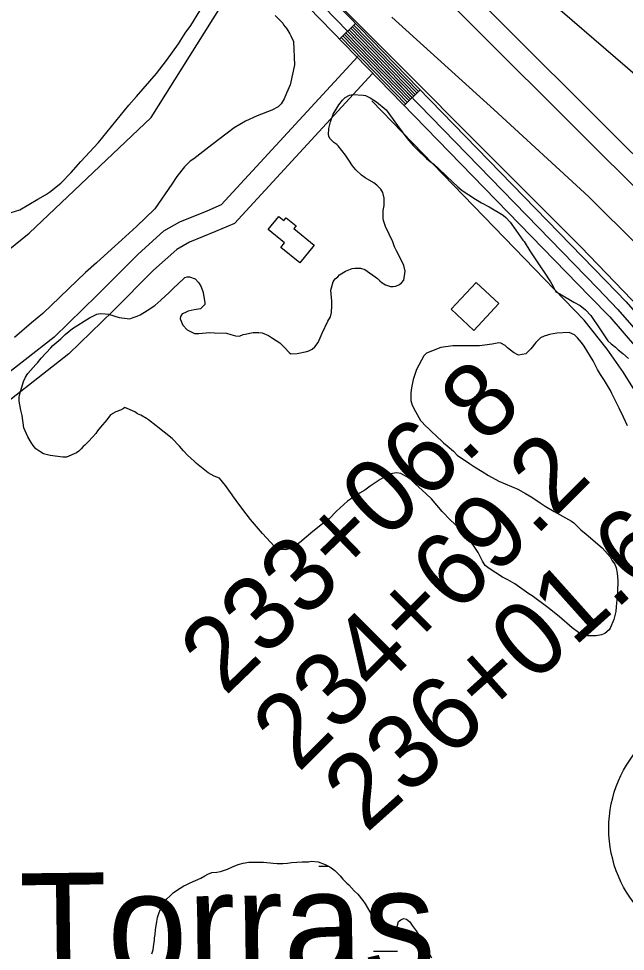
# Model space of a CAD drawing. Extents: x 3146026 to 3183936, y 897894 to 923344.
# Drawn here: x 3171939 to 3172756, y 904310 to 905566 of the extents above; entities that cross this region are included whole.
import ezdxf

# ---------------------------------------------------------------- set-up
doc = ezdxf.new("R2010")
doc.units = 0
for name, color, linetype in [('V-BLDG-OTLN', 7, 'Continuous'), ('V-LEVE-TOET', 7, 'Continuous'), ('V-ROAD-CNTR', 7, 'Continuous'), ('V-ROAD-IDEN', 7, 'Continuous'), ('V-SITE-VEGE', 7, 'Continuous'), ('V-SURV-IDEN', 7, 'Continuous'), ('V-SURV-LINE', 7, 'Continuous'), ('V-TOPO-GNAM-IDEN', 7, 'Continuous'), ('V-TOPO-SHOR', 7, 'Continuous'), ('V-WETL-SWMP', 7, 'Continuous')]:
    doc.layers.add(name, color=color, linetype=linetype)

msp = doc.modelspace()

# ---------------------------------------------------------------- linework, layer by layer
at = {"layer": 'V-BLDG-OTLN'}
for points in [[(3172275, 905281.9), (3172289.4, 905299.6), (3172296, 905294.2), (3172299.1, 905298), (3172312.7, 905287.1), (3172309.6, 905283.3), (3172337, 905261.1), (3172317.5, 905237.1), (3172292, 905257.7), (3172297.1, 905264)], [(3172552, 905146.3), (3172521.5, 905174.7), (3172555.3, 905210.8), (3172585.7, 905182.4)]]:
    msp.add_lwpolyline(points, close=True, dxfattribs=at)
at = {"layer": 'V-LEVE-TOET'}
for points in [[(3172529.3, 905786.4), (3172531.3, 905781.5), (3172531.4, 905768.5), (3172528.9, 905753.2), (3172526.2, 905732.1), (3172532.9, 905716.1), (3172545.6, 905698.2), (3172564.6, 905678.8), (3172610, 905628.6), (3172788.2, 905474.5), (3172938.4, 905328), (3173044.4, 905215.5), (3173079.4, 905167.6), (3173157, 905054.6), (3173211.7, 904943.1), (3173306.6, 904778.2), (3173401.4, 904667.1), (3173480.5, 904547.5), (3173582.5, 904366.5)], [(3173393.9, 904268.1), (3173391.5, 904277.3), (3173381.5, 904302.7), (3173333.9, 904388.2), (3173230.5, 904565), (3173129.1, 904747.2), (3173057.9, 904869.1), (3172963.8, 905015.7), (3172850.9, 905169.6), (3172773.3, 905260.1), (3172706.8, 905326.1), (3172578.8, 905443.6), (3172441.8, 905567.9)]]:
    msp.add_lwpolyline(points, dxfattribs=at)
at = {"layer": 'V-ROAD-CNTR'}
for p, q in [((3172392.7, 905559.4), (3172371.2, 905538.5)), ((3172479.9, 905469.9), (3172458.4, 905448.9))]:
    msp.add_line(p, q, dxfattribs=at)
for points in [[(3171485.1, 906491), (3171511.5, 906466.1), (3171767.2, 906202.4), (3172729.8, 905213), (3172757.1, 905184.7), (3172794.3, 905142), (3172820.4, 905108.8), (3172848.9, 905069.2)], [(3171474.8, 906480.1), (3171501, 906455.4), (3171756.4, 906191.9), (3172719.1, 905202.5), (3172746, 905174.6), (3172782.8, 905132.4), (3172808.4, 905099.8), (3172836.8, 905060.4)], [(3171464.5, 906469.2), (3171490.4, 906444.7), (3171745.7, 906181.5), (3172708.3, 905192.1), (3172735, 905164.5), (3172771.2, 905122.8), (3172796.5, 905090.8), (3172824.6, 905051.6)], [(3172386.3, 905553.2), (3172473.4, 905463.6)], [(3172388.4, 905555.3), (3172475.6, 905465.7)], [(3172390.6, 905557.4), (3172477.7, 905467.8)], [(3172373.4, 905540.6), (3172460.5, 905451)], [(3172375.5, 905542.7), (3172462.7, 905453.1)], [(3172377.7, 905544.8), (3172464.8, 905455.2)], [(3172379.8, 905546.9), (3172467, 905457.3)], [(3172382, 905549), (3172469.1, 905459.4)], [(3172384.1, 905551.1), (3172471.3, 905461.5)], [(3172396, 905515), (3172211.9, 905315.3), (3172192.5, 905307), (3172155.8, 905292), (3172134.3, 905279.8), (3172100.1, 905248.9), (3172044.7, 905193.6), (3171987, 905137.1), (3171869.2, 905045.4), (3171843.9, 905026.8), (3171662.8, 904836), (3171344.9, 904497.8), (3171046.7, 904177.6), (3170924, 904055.8), (3170905, 904037), (3170884.8, 904020.2), (3170828.3, 903983.6), (3170772.5, 903951.5), (3170747.9, 903934.6), (3170726, 903916.2), (3170692.1, 903883.8), (3170452.4, 903624.8)], [(3172415.7, 905492.1), (3172229.6, 905290.3), (3172204.1, 905279.4), (3172169, 905264.9), (3172152, 905255.3), (3172120.8, 905227.2), (3172065.8, 905172.2), (3172006.8, 905114.5), (3171887.3, 905021.5), (3171863.9, 905004.2), (3171684.6, 904815.4), (3171366.8, 904477.3), (3171068.2, 904156.7), (3170945.1, 904034.5), (3170925.2, 904014.7), (3170902.5, 903996), (3170844, 903958), (3170788.5, 903926.1), (3170766, 903910.7), (3170746, 903893.9), (3170713.5, 903862.8), (3170474.1, 903604)]]:
    msp.add_lwpolyline(points, dxfattribs=at)
at = {"layer": 'V-ROAD-IDEN'}
msp.add_circle((3172898.8, 904475.6), 165, dxfattribs=at)
at = {"layer": 'V-SITE-VEGE'}
for points in [[(3172284.4, 905570.1), (3172294.9, 905560), (3172295.8, 905557.6), (3172300.1, 905552.3), (3172304.4, 905545.5), (3172305.8, 905542.7), (3172309.1, 905535), (3172310.4, 905503.8), (3172308.9, 905495.2), (3172304.5, 905477), (3172299.6, 905465.5), (3172296.7, 905457.8), (3172292.8, 905451.1), (3172288.5, 905447.3), (3172279.8, 905442.6), (3172260.1, 905435), (3172244.7, 905427.9), (3172229.3, 905418.9), (3172219.7, 905411.7), (3172199, 905396), (3172174.9, 905377.4), (3172170.1, 905374.1), (3172162.4, 905366.5), (3172152.2, 905353.6), (3172145.5, 905343.1), (3172122.3, 905310.1), (3172097.7, 905286.2), (3172077.9, 905268.1), (3172063.9, 905255.7), (3172043.7, 905237.1), (3172029.2, 905224.3), (3171971.8, 905169), (3171956.4, 905156.6), (3171933.7, 905136.5)], [(3172022.8, 905373.5), (3172046.5, 905399.2), (3172087.5, 905449.4), (3172097.7, 905461.3), (3172124.7, 905492.3), (3172138.2, 905509.5), (3172154.2, 905532), (3172163.4, 905546.3), (3172171.1, 905556.8), (3172183.2, 905576.4)], [(3172202.9, 905143.2), (3172218.9, 905142.4), (3172224.6, 905140.6), (3172231, 905138.8), (3172236, 905138.4), (3172239.6, 905139.8), (3172241.4, 905140.9), (3172243.9, 905141.2), (3172255, 905143.3), (3172262.5, 905143.6), (3172267.1, 905142.9), (3172275.3, 905139.3), (3172281, 905136), (3172290.9, 905129.5), (3172294.8, 905125.6), (3172296.9, 905123.1), (3172303.3, 905116.3), (3172305.8, 905114.5), (3172314, 905115.1), (3172327.2, 905117.9), (3172329.7, 905118.6), (3172334.4, 905121.1), (3172337.9, 905124.3), (3172342.2, 905130), (3172347.7, 905142.4), (3172355.6, 905158.8), (3172358.8, 905164.5), (3172360.3, 905170.2), (3172360.7, 905179.8), (3172360.7, 905185.8), (3172359.4, 905200.5), (3172362.7, 905211.5), (3172364.1, 905214), (3172365.5, 905215.8), (3172368.8, 905218.6), (3172371.3, 905221.1), (3172379.2, 905226), (3172388.1, 905229.5), (3172392, 905230.2), (3172399.5, 905230.2), (3172405.2, 905228.4), (3172422.2, 905216.2), (3172425.4, 905212.9), (3172428.6, 905210.4), (3172432.9, 905207.5), (3172440, 905205.4), (3172443.2, 905205.3), (3172446.8, 905206), (3172451.8, 905208.2), (3172454.7, 905210.3), (3172457.9, 905213.8), (3172459.7, 905225.9), (3172457.6, 905233.8), (3172453.8, 905242), (3172447.8, 905253.5), (3172445.3, 905258.8), (3172442.8, 905265.3), (3172433, 905286.3), (3172430.5, 905294.2), (3172429.8, 905297.4), (3172429.9, 905307.8), (3172431.3, 905314.2), (3172431.4, 905324.5), (3172429.7, 905332), (3172426.8, 905336.3), (3172421.2, 905342), (3172417.3, 905344.9), (3172405.9, 905351.7), (3172400.9, 905355.3), (3172393.1, 905362.5), (3172388.5, 905367.9), (3172383.6, 905375.4), (3172379.3, 905382.2), (3172369.4, 905394.7), (3172367.6, 905396.5), (3172363.7, 905399.4), (3172361.2, 905401.6), (3172358, 905404.8), (3172356.6, 905407.6), (3172356.3, 905410.1), (3172356.7, 905418), (3172358.9, 905427.2), (3172362.5, 905437.2), (3172369, 905447.9), (3172370.1, 905450), (3172375.1, 905456), (3172378.7, 905459.6), (3172384.8, 905462.8), (3172389, 905463.8), (3172402.9, 905463), (3172406.1, 905462.3), (3172412.5, 905459.4), (3172421.1, 905454), (3172433.8, 905443.2), (3172449.4, 905422.1), (3172461.8, 905404.9), (3172470.3, 905395.2), (3172476, 905389.2), (3172488.4, 905377.7), (3172493.4, 905373.7), (3172498, 905370.1)], [(3171917.4, 905301.2), (3171940.5, 905308.7), (3171965, 905323), (3171975.1, 905328.7), (3171980.4, 905332.5), (3171995.8, 905344.4), (3172009.8, 905358.7), (3172022.8, 905373.5)], [(3172498, 905370.1), (3172504, 905364.8), (3172515.7, 905353.6), (3172530.3, 905339.6), (3172536.3, 905334.6), (3172554.4, 905322.8), (3172562.2, 905318.1), (3172572.9, 905312.7), (3172591.7, 905301.2), (3172595.3, 905298.3), (3172600.9, 905291.8), (3172608.4, 905281.4), (3172617.9, 905267.8), (3172619.7, 905266.1), (3172627.5, 905253.2), (3172641.6, 905231.7), (3172646.9, 905224.5), (3172655.4, 905211.7), (3172658.9, 905205.2)], [(3172219.9, 904934.2), (3172217.8, 904937.4), (3172213.6, 904942.4), (3172209.7, 904947.4), (3172202.5, 904950), (3172194.4, 904954.6), (3172178.4, 904967.2), (3172175.6, 904970.1), (3172166.3, 904978.3), (3172161, 904984.1), (3172155.7, 904990.5), (3172145.8, 905000.9), (3172124.1, 905017.8), (3172113.8, 905026), (3172111.3, 905027.8), (3172103.5, 905032.2), (3172099.2, 905034), (3172095.7, 905036.5), (3172082.2, 905042.6), (3172080.4, 905041.2), (3172076.1, 905039.1), (3172070, 905036.6), (3172062.9, 905032.4), (3172057.8, 905026), (3172049.2, 905016.1), (3172045.3, 905011.1), (3172042.8, 905007.5), (3172038.8, 905002.9), (3172032.7, 904996.2), (3172028.1, 904991.9), (3172025.9, 904989.8), (3172023.4, 904987), (3172020.2, 904983.8), (3172016.9, 904981.3), (3172003.7, 904975.7), (3171998.4, 904975.7), (3171981.6, 904977.9), (3171972.4, 904980.1), (3171967.4, 904983.4), (3171962.4, 904987), (3171958.5, 904991.3), (3171956.1, 904995.2), (3171951.5, 905003.1), (3171946.2, 905015.2), (3171943.8, 905031.6), (3171942, 905039.1), (3171939.6, 905050.9), (3171939.6, 905056.3), (3171940.7, 905060.9), (3171945.5, 905077.3), (3171948.3, 905083.3), (3171951.6, 905088.3), (3171962, 905100.3), (3171964.5, 905102.8), (3171969.2, 905108.9), (3171982.4, 905122.7), (3171985.3, 905125.9), (3171995.7, 905134.7), (3172001.8, 905140.8), (3172011.8, 905148.9), (3172034.4, 905163.1), (3172044.4, 905168), (3172049, 905169), (3172055.4, 905168.6), (3172060.1, 905167.9), (3172074.3, 905163.5), (3172088.9, 905162), (3172093.2, 905163.8), (3172098.6, 905165.6), (3172102.5, 905167.3), (3172112.1, 905173), (3172122.5, 905180), (3172126.5, 905183.2), (3172130.4, 905186.8), (3172136.9, 905192.8), (3172141.2, 905196.7), (3172146.9, 905202), (3172154.8, 905209.8), (3172161.2, 905215.5), (3172163, 905217.3), (3172165.9, 905218.3), (3172169.1, 905218.3), (3172176.9, 905215.7), (3172181.9, 905210.4), (3172184.7, 905205), (3172187.5, 905197.1), (3172189.6, 905183.2), (3172189.6, 905181.1), (3172183.8, 905175.4), (3172175.3, 905174), (3172167.4, 905172.3), (3172162.8, 905169.8), (3172159.2, 905168.4), (3172157, 905165.2), (3172156.7, 905161.7), (3172160.2, 905153.1), (3172166.2, 905147), (3172175.8, 905142.3), (3172181.5, 905142.3), (3172196.5, 905143.3), (3172202.9, 905143.2)], [(3172658.9, 905205.2), (3172662.5, 905198.1), (3172667.8, 905195.5), (3172686.6, 905184.4), (3172695.2, 905179.7), (3172702.6, 905174), (3172709.7, 905166.1), (3172721.7, 905148.5), (3172732.7, 905132.4), (3172737, 905128.1), (3172742.6, 905123.5), (3172746.2, 905120.2), (3172752.6, 905115.2), (3172760.4, 905108.4)], [(3172758.8, 905017.8), (3172753.5, 905029.3), (3172747.9, 905041.4), (3172738, 905061.1), (3172735.9, 905065.4), (3172728.1, 905079), (3172722.5, 905086.8), (3172718.6, 905093.6), (3172712.6, 905105.1), (3172700.6, 905125.1), (3172697, 905129.8), (3172691.7, 905136.2), (3172687.8, 905140.2), (3172680.3, 905143.4), (3172663.9, 905142.4), (3172653.9, 905140.7), (3172651.1, 905140), (3172646.8, 905138.6), (3172641.8, 905136.1), (3172635.7, 905129.8), (3172628.9, 905121.6), (3172622.1, 905114.9), (3172612.1, 905113.1), (3172605.3, 905116.4), (3172597.5, 905122.8), (3172594.3, 905126.1), (3172588.3, 905129.3), (3172585.8, 905129.7), (3172576.9, 905127.9), (3172559.7, 905125.5), (3172540.1, 905125.7), (3172531.6, 905125.3), (3172523.7, 905125.4), (3172507.7, 905123.3)], [(3172507.7, 905123.3), (3172488.4, 905115.6), (3172484.8, 905112.1), (3172474.7, 905093.6), (3172470.3, 905080), (3172468.1, 905069), (3172467, 905062.2), (3172467.3, 905051.9), (3172469.1, 905045.5), (3172473.3, 905037.2), (3172480.4, 905025.1), (3172481.8, 905023.3), (3172486.7, 905018.3), (3172492.1, 905013.2), (3172496.3, 905008.9), (3172500.6, 905005.4), (3172511.2, 904995), (3172516.2, 904991), (3172524.7, 904983.5), (3172529.7, 904978.4), (3172546, 904966.9), (3172552.8, 904962.6), (3172563.4, 904956.2), (3172571.9, 904950.8), (3172585.8, 904943.5), (3172611.4, 904932.4), (3172621.7, 904926.9), (3172630.3, 904921.9), (3172641.3, 904914), (3172648, 904909.7), (3172660.1, 904902.5), (3172683.6, 904889.5), (3172686.8, 904887), (3172696.3, 904877.7), (3172703.1, 904871.9), (3172724.7, 904853.6), (3172735.4, 904841.5), (3172738.5, 904836.1), (3172741.7, 904831.4), (3172743.8, 904826.8), (3172745.2, 904819.3), (3172745.9, 904809.7), (3172745.4, 904794), (3172744.7, 904786.5), (3172744.7, 904783.6), (3172743.5, 904774.4), (3172743.2, 904768), (3172740.6, 904756.9), (3172735.5, 904745.2), (3172734.1, 904743), (3172728.4, 904738.4), (3172724.1, 904736.3), (3172716.9, 904734.9), (3172705.5, 904735), (3172695.6, 904738.3), (3172693.1, 904739.7), (3172684.6, 904745.8), (3172666.8, 904760.9), (3172651.9, 904773.1), (3172630.6, 904788.9), (3172626.3, 904791.4), (3172607.1, 904805.1), (3172597.6, 904810.5), (3172590.8, 904814.1), (3172572.7, 904825.6), (3172567.4, 904829.9), (3172563.8, 904835.6), (3172557.8, 904847.1), (3172543, 904869.3), (3172525.2, 904886.8), (3172520.6, 904890.8), (3172509.6, 904902.3), (3172502.2, 904910.9), (3172494.8, 904919.5), (3172488, 904926.3), (3172472.4, 904940.3), (3172467.1, 904945.6), (3172461.8, 904949.2), (3172453.6, 904953.6), (3172447.9, 904954.7), (3172440, 904953.3), (3172426.1, 904945.5), (3172412.5, 904936.7), (3172405.3, 904931.4), (3172398.2, 904927.1), (3172381.7, 904916.5), (3172367, 904903.1), (3172357, 904892.8), (3172348.4, 904885.7), (3172335.1, 904875.4), (3172317.2, 904860.5), (3172303.6, 904852.4), (3172298.6, 904851), (3172293.3, 904851.4), (3172289, 904852.9), (3172283.7, 904855.4), (3172267.4, 904872.9), (3172251.4, 904891.9), (3172245.4, 904899.4), (3172234.1, 904914.1), (3172219.9, 904934.2)]]:
    msp.add_lwpolyline(points, dxfattribs=at)
at = {"layer": 'V-SURV-LINE'}
for points in [[(3171543.6, 906601.3), (3172818.3, 905332.2)], [(3172797.1, 905310.9), (3171522.5, 906580.1)]]:
    msp.add_lwpolyline(points, dxfattribs=at)
at = {"layer": 'V-TOPO-SHOR'}
for points in [[(3172320, 905635.7), (3172695.9, 905258.6), (3172810.7, 905139.8), (3172831.6, 905107.1), (3172930, 904956.6), (3173158.2, 904588.6), (3173306.9, 904342.7), (3173329.1, 904321.4), (3173354.5, 904305.2)], [(3171841.8, 905187.2), (3171953.1, 905277), (3172117.5, 905433), (3172220.8, 905597.4)], [(3173192.1, 904382.9), (3173075.2, 904578.4), (3172922.4, 904824.5), (3172815, 904990.7), (3172753.5, 905089.5), (3172731.6, 905121.1), (3172700.6, 905160.2), (3172606.9, 905256.8), (3172414.6, 905455.3)]]:
    msp.add_lwpolyline(points, dxfattribs=at)
at = {"layer": 'V-WETL-SWMP'}
for p, q in [((3172220.4, 904420.8), (3172227.2, 904423.9)), ((3172227.2, 904423.9), (3172234.7, 904427.1)), ((3172234.7, 904427.1), (3172241.5, 904428.9)), ((3172241.5, 904428.9), (3172249, 904430.2)), ((3172249, 904430.2), (3172257.2, 904430.2)), ((3172257.2, 904430.2), (3172261.8, 904430.5)), ((3172261.8, 904430.5), (3172268.9, 904430.5)), ((3172268.9, 904430.5), (3172277.9, 904429.7)), ((3172277.9, 904429.7), (3172281.8, 904429)), ((3172281.8, 904429), (3172287.1, 904428.6)), ((3172287.1, 904428.6), (3172295, 904428.6)), ((3172295, 904428.6), (3172301, 904428.9)), ((3172301, 904428.9), (3172306.7, 904429.9)), ((3172306.7, 904429.9), (3172313.5, 904430.6)), ((3172313.5, 904430.6), (3172320.7, 904430.9)), ((3172320.7, 904430.9), (3172329.2, 904430.9)), ((3172329.2, 904430.9), (3172333.1, 904431.6)), ((3172333.1, 904431.6), (3172342.4, 904430.8)), ((3172342.4, 904430.8), (3172352, 904427.2)), ((3172343.3, 904425.1), (3172356.1, 904425.2)), ((3172352, 904427.2), (3172358.1, 904424.3)), ((3172358.1, 904424.3), (3172364.8, 904419.3)), ((3172184.3, 904408.9), (3172189.7, 904412)), ((3172189.7, 904412), (3172194, 904414.1)), ((3172194, 904414.1), (3172199, 904416.3)), ((3172199, 904416.3), (3172206.1, 904416.9)), ((3172206.1, 904416.9), (3172211.1, 904417.6)), ((3172211.1, 904417.6), (3172220.4, 904420.8)), ((3172364.8, 904419.3), (3172371.9, 904412.1)), ((3172371.9, 904412.1), (3172375.8, 904407.4)), ((3172156.4, 904395.5), (3172161.4, 904398.3)), ((3172161.4, 904398.3), (3172164.7, 904399.7)), ((3172164.7, 904399.7), (3172170, 904402.5)), ((3172170, 904402.5), (3172184.3, 904408.9)), ((3172375.8, 904407.4), (3172381.1, 904402.1)), ((3172381.1, 904402.1), (3172383.6, 904399.9)), ((3172383.6, 904399.9), (3172391, 904391.7)), ((3172142.8, 904384.5), (3172147.8, 904389.4)), ((3172147.8, 904389.4), (3172156.4, 904395.5)), ((3172391, 904391.7), (3172395.6, 904387.4)), ((3172395.6, 904387.4), (3172402.7, 904378.8)), ((3172132.1, 904371), (3172136.7, 904378.5)), ((3172136.7, 904378.5), (3172138.5, 904380.9)), ((3172138.5, 904380.9), (3172142.8, 904384.5)), ((3172402.7, 904378.8), (3172405.6, 904374.5)), ((3172405.6, 904374.5), (3172411.9, 904363.7)), ((3172125.9, 904356), (3172128.1, 904362.8)), ((3172128.1, 904362.8), (3172129.9, 904367.1)), ((3172129.9, 904367.1), (3172132.1, 904371)), ((3172411.9, 904363.7), (3172417.6, 904353.7)), ((3172123.3, 904339.3), (3172125.2, 904350.7)), ((3172125.2, 904350.7), (3172125.9, 904356)), ((3172417.6, 904353.7), (3172422.2, 904347.6)), ((3172422.2, 904347.6), (3172424.6, 904344.8)), ((3172448.5, 904341.8), (3172450.4, 904350.7)), ((3172450.4, 904350.7), (3172453.9, 904352.8)), ((3172453.9, 904352.8), (3172457.5, 904354.6)), ((3172457.5, 904354.6), (3172461.4, 904353.8)), ((3172461.4, 904353.8), (3172466, 904349.9)), ((3172466, 904349.9), (3172468.9, 904344.9)), ((3172122.9, 904332.9), (3172123.3, 904339.3)), ((3172424.6, 904344.8), (3172431.4, 904336.2)), ((3172431.4, 904336.2), (3172435.6, 904333.3)), ((3172443.5, 904333.6), (3172446, 904336.1)), ((3172446, 904336.1), (3172448.5, 904341.8)), ((3172468.9, 904344.9), (3172474.2, 904338.1)), ((3172474.2, 904338.1), (3172478.8, 904330.9)), ((3172121.1, 904320.1), (3172122.2, 904325)), ((3172122.2, 904328.6), (3172122.9, 904332.9)), ((3172122.2, 904325), (3172122.2, 904328.6)), ((3172435.6, 904333.3), (3172443.5, 904333.6)), ((3172478.8, 904330.9), (3172482.3, 904324.1)), ((3172482.3, 904324.1), (3172484.1, 904321.6)), ((3172118.5, 904306.9), (3172120, 904312.2)), ((3172120, 904312.2), (3172121.1, 904320.1)), ((3172417.1, 904310.4), (3172449.1, 904310.7)), ((3172484.1, 904321.6), (3172486.5, 904317)), ((3172486.5, 904317), (3172490.1, 904311.2)), ((3172490.1, 904311.2), (3172495, 904301.6))]:
    msp.add_line(p, q, dxfattribs=at)

# ---------------------------------------------------------------- texts
at = {"layer": 'V-SURV-IDEN'}
for s, rotation, p in [('233+06.8', 44.0089, (3172216.9, 904652.8)), ('234+69.2', 44.9068, (3172315.6, 904549.7)), ('236+01.6', 41.8556, (3172407, 904468.4))]:
    msp.add_text(s, height=100, rotation=rotation, dxfattribs=at).set_placement(p)
at = {"layer": 'V-TOPO-GNAM-IDEN'}
msp.add_text('Torras', height=145, rotation=0.7094, dxfattribs=at).set_placement((3171940.8, 904270.2))

doc.saveas('drawing.dxf')
